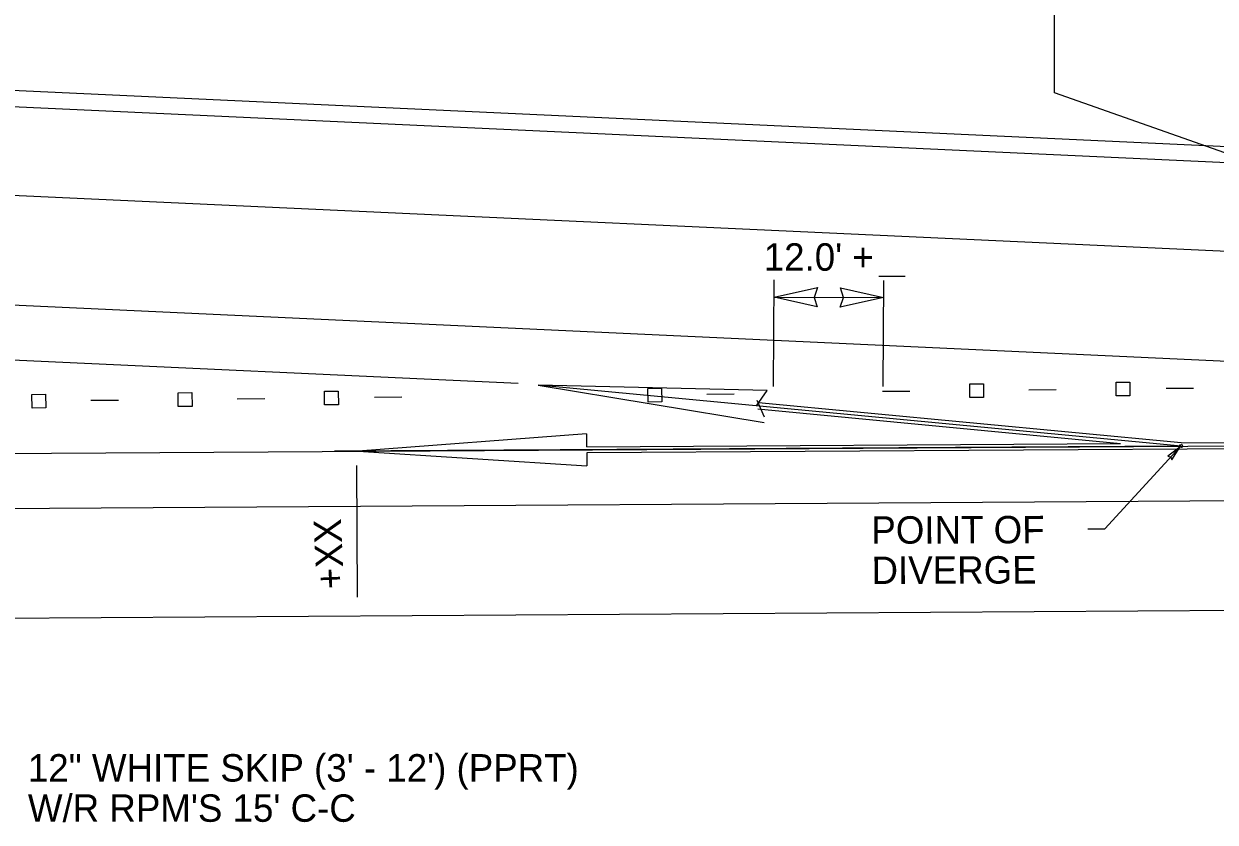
# Model space of a CAD drawing. Extents: x 538465 to 539103, y 1527987 to 1528392.
# Drawn here: x 538676.5 to 538806.8, y 1528230.3 to 1528317.6 of the extents above; entities that cross this region are included whole.
import ezdxf

# ---------------------------------------------------------------- set-up
doc = ezdxf.new("R2010")
doc.units = 0
for name, color, linetype in [('CL_dp', 7, 'Continuous'), ('Default', 7, 'Continuous'), ('DimLines_dp', 7, 'Continuous'), ('DirArrowsPavt', 7, 'Continuous'), ('LeaderLine_dp', 7, 'Continuous'), ('PMStripe6W(10-30)', 7, 'Continuous')]:
    doc.layers.add(name, color=color, linetype=linetype)

msp = doc.modelspace()

# ---------------------------------------------------------------- linework, layer by layer
at = {"layer": 'CL_dp'}
for p, q in [((538601.29, 1528284.26), (538730.57, 1528278.29)), ((538803.07, 1528271.41), (538732.75, 1528278.08)), ((538611.16, 1528270.2), (538818.07, 1528271.49)), ((538803.07, 1528271.41), (538710.49, 1528270.84))]:
    msp.add_line(p, q, dxfattribs=at)
at = {"layer": 'Default'}
for p, q in [((538550.39, 1528316.09), (538853.15, 1528302.11)), ((538549.84, 1528314.35), (538852.95, 1528300.36)), ((538547.55, 1528304.74), (538858.35, 1528290.39)), ((538547.91, 1528292.72), (538858.28, 1528278.39)), ((538804.42, 1528277.72), (538801.42, 1528277.69)), ((538686.86, 1528276.41), (538683.86, 1528276.38)), ((538702.86, 1528276.58), (538699.86, 1528276.55)), ((538717.86, 1528276.74), (538714.86, 1528276.71)), ((538754.21, 1528277.07), (538751.21, 1528277.04)), ((538773.42, 1528277.39), (538770.42, 1528277.36)), ((538789.42, 1528277.56), (538786.42, 1528277.53))]:
    msp.add_line(p, q, dxfattribs=at)
for points in [[(538744.76, 1528277.72), (538746.26, 1528277.74), (538746.28, 1528276.24), (538744.78, 1528276.22)], [(538779.96, 1528278.22), (538781.46, 1528278.23), (538781.47, 1528276.73), (538779.97, 1528276.72)], [(538795.96, 1528278.39), (538797.46, 1528278.4), (538797.47, 1528276.9), (538795.97, 1528276.89)], [(538677.4, 1528277.06), (538678.9, 1528277.08), (538678.91, 1528275.58), (538677.41, 1528275.56)], [(538693.4, 1528277.23), (538694.9, 1528277.25), (538694.91, 1528275.75), (538693.41, 1528275.73)], [(538709.4, 1528277.4), (538710.9, 1528277.42), (538710.91, 1528275.92), (538709.41, 1528275.9)]]:
    msp.add_lwpolyline(points, close=True, dxfattribs=at)
at = {"layer": 'DimLines_dp'}
for p, q in [((538758.53, 1528289.58), (538758.46, 1528277.94)), ((538770, 1528289.98), (538772.91, 1528289.98)), ((538770.53, 1528289.51), (538770.46, 1528277.94)), ((538758.56, 1528287.68), (538763.31, 1528288.75)), ((538763.31, 1528288.75), (538762.93, 1528287.67)), ((538766.15, 1528287.66), (538765.82, 1528288.71)), ((538765.82, 1528288.71), (538770.53, 1528287.66)), ((538763.27, 1528286.63), (538758.56, 1528287.68)), ((538758.56, 1528287.68), (538770.53, 1528287.66)), ((538762.93, 1528287.67), (538763.27, 1528286.63)), ((538770.53, 1528287.66), (538765.77, 1528286.59)), ((538765.77, 1528286.59), (538766.15, 1528287.66)), ((538802.94, 1528271.3), (538794.73, 1528262.36)), ((538802.92, 1528271.28), (538801.62, 1528270.32)), ((538802.06, 1528269.91), (538802.92, 1528271.28)), ((538801.62, 1528270.32), (538801.93, 1528270.2)), ((538801.93, 1528270.2), (538802.06, 1528269.91)), ((538713.02, 1528254.88), (538712.93, 1528269.28)), ((538792.87, 1528262.35), (538794.73, 1528262.36))]:
    msp.add_line(p, q, dxfattribs=at)
msp.add_circle((538803.07, 1528271.41), 0.171, dxfattribs=at)
at = {"layer": 'DirArrowsPavt'}
for p, q in [((538757.8, 1528277.47), (538732.75, 1528278.08)), ((538732.75, 1528278.08), (538757.47, 1528273.98)), ((538756.64, 1528275.82), (538757.8, 1528277.47)), ((538757.51, 1528274.56), (538756.7, 1528276.41)), ((538756.8, 1528275.47), (538796.46, 1528271.7)), ((538803.08, 1528271.75), (538756.86, 1528276.13)), ((538738.04, 1528272.76), (538713.07, 1528270.85)), ((538738.04, 1528272.76), (538738.04, 1528271.32)), ((538738.07, 1528271.34), (538796.46, 1528271.7)), ((538803.08, 1528271.75), (538818.06, 1528271.84)), ((538713.07, 1528270.85), (538738.08, 1528269.26)), ((538818.07, 1528271.17), (538738.07, 1528270.67)), ((538738.07, 1528270.67), (538738.08, 1528269.26))]:
    msp.add_line(p, q, dxfattribs=at)
at = {"layer": 'LeaderLine_dp'}
for p, q in [((538789.22, 1528310.05), (538789.22, 1528319.1)), ((538853.51, 1528287.34), (538789.22, 1528310.05))]:
    msp.add_line(p, q, dxfattribs=at)
at = {"layer": 'PMStripe6W(10-30)'}
for p, q in [((538571.06, 1528263.95), (539020.96, 1528266.76)), ((538571.13, 1528251.96), (539021.04, 1528254.76))]:
    msp.add_line(p, q, dxfattribs=at)

# ---------------------------------------------------------------- texts
at = {"layer": 'DimLines_dp'}
for s, p in [("12.0' +", (538757.43, 1528290.59)), ('12" WHITE SKIP (3\' - 12\') (PPRT)', (538676.96, 1528234.71)), ("W/R RPM'S 15' C-C", (538676.96, 1528230.31))]:
    msp.add_text(s, height=3, dxfattribs=at).set_placement(p)
for s, rotation, p in [('+XX', 92.6209, (538711.54, 1528255.82)), ('POINT OF', 0.1761, (538769.2, 1528260.72)), ('DIVERGE', 0.1761, (538769.22, 1528256.32))]:
    msp.add_text(s, height=3, rotation=rotation, dxfattribs=at).set_placement(p)

doc.saveas('drawing.dxf')
